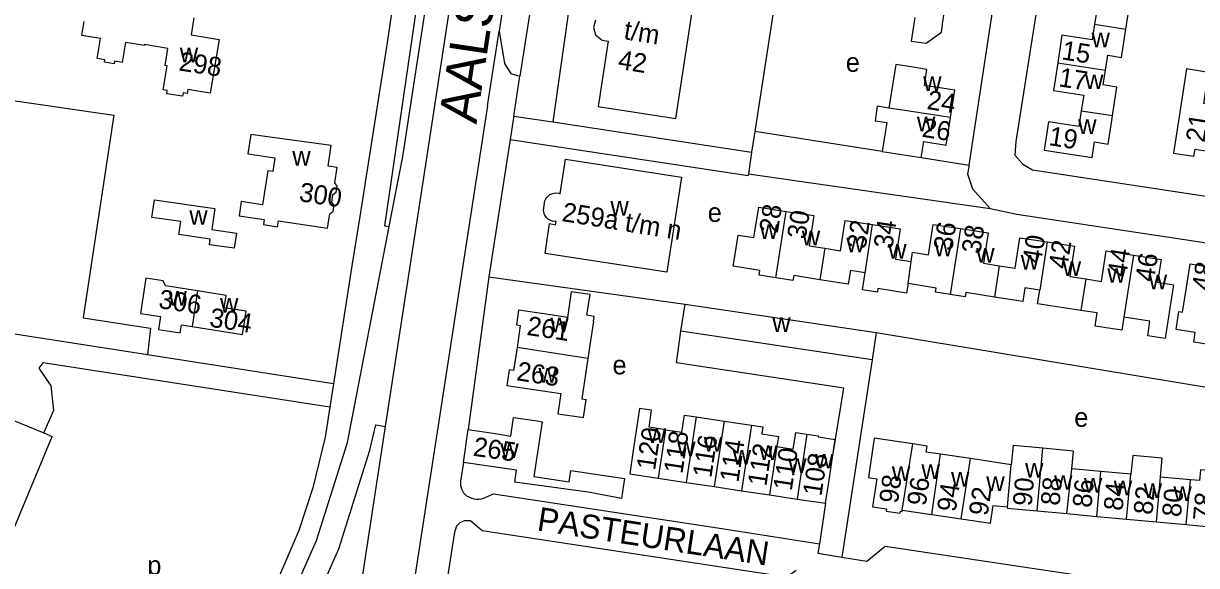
# Model space of a CAD drawing. Extents: x 161093 to 163177, y 379000 to 380904.
# Drawn here: x 161584.6 to 161831.1, y 380571.5 to 380685.4 of the extents above; entities that cross this region are included whole.
import ezdxf

# ---------------------------------------------------------------- set-up
doc = ezdxf.new("R2010")
doc.units = 0
for name, color, linetype in [('BLT_Basislijn', 7, 'Continuous'), ('BLT_Bebouwing', 7, 'Continuous'), ('BLT_Centroide', 7, 'Continuous'), ('BLT_Huisnummer', 7, 'Continuous'), ('BLT_Huisnummer_ tussenligend', 7, 'Continuous'), ('BLT_Huisnummer_reeks', 7, 'Continuous'), ('BLT_Onderverdeling_panden', 7, 'Continuous'), ('BLT_Straatnaam', 7, 'Continuous'), ('BLT_Straatnaam_hoofdweg', 7, 'Continuous'), ('BLT_Vlakafsluiter', 7, 'Continuous')]:
    doc.layers.add(name, color=color, linetype=linetype)

msp = doc.modelspace()

# ---------------------------------------------------------------- linework, layer by layer
at = {"layer": 'BLT_Basislijn'}
for p, q in [((161712.32, 380779.37), (161695.84, 380664.67)), ((161699.21, 380740.85), (161688.95, 380674.32)), ((161665.83, 380714.11), (161661.04, 380681.33)), ((161745.18, 380707.38), (161738.3, 380662.64)), ((161687.6, 380665.55), (161686.89, 380660.96)), ((161687.65, 380665.91), (161687.6, 380665.55)), ((161687.65, 380665.91), (161695.84, 380664.67)), ((161695.84, 380664.67), (161737.65, 380658.36)), ((161738.3, 380662.64), (161737.65, 380658.36)), ((161765.09, 380658.46), (161738.3, 380662.64)), ((161686.89, 380660.96), (161686.55, 380658.75)), ((161686.89, 380660.96), (161736.91, 380653.41)), ((161686.55, 380658.75), (161682.45, 380632.16)), ((161737.56, 380657.76), (161736.97, 380653.81)), ((161737.65, 380658.36), (161737.56, 380657.76)), ((161773.27, 380657.19), (161783.33, 380655.62)), ((161736.97, 380653.81), (161736.91, 380653.41)), ((161736.97, 380653.81), (161787.8, 380646.51)), ((161653.62, 380634.48), (161649.78, 380609.69)), ((161682.45, 380632.16), (161678.11, 380600.05)), ((161682.45, 380632.16), (161723.65, 380626.43)), ((161610.72, 380615.75), (161577.46, 380620.91)), ((161611.34, 380621.33), (161610.72, 380615.75)), ((161763.82, 380620.43), (161846.89, 380606.73)), ((161649.78, 380609.69), (161610.72, 380615.75)), ((161762.96, 380614.72), (161756.59, 380573.27)), ((161649.02, 380604.75), (161588.78, 380614.09)), ((161649.78, 380609.69), (161649.02, 380604.75)), ((161574.73, 380560.34), (161590.62, 380598.62)), ((161588.93, 380599.39), (161590.62, 380598.62)), ((161753.18, 380584.58), (161751.88, 380576.03)), ((161675.17, 380578.54), (161663.42, 380502.41)), ((161730.45, 380579.4), (161751.88, 380576.03)), ((161751.88, 380576.03), (161751.59, 380574.09)), ((161765.74, 380575.56), (161840.27, 380564.46)), ((161751.59, 380574.09), (161756.59, 380573.27))]:
    msp.add_line(p, q, dxfattribs=at)
for points in [[(161706.18, 380821.7), (161704.99, 380816.11), (161684.56, 380683.72)], [(161669.3, 380656.68), (161678.84, 380718.93), (161681.03, 380733.18), (161681.5, 380742.87), (161681.03, 380752.86), (161679.79, 380769.7), (161680.11, 380781.48), (161684.7, 380816.97)], [(161661.49, 380642.68), (161664.36, 380657.44), (161676.05, 380733.69), (161676.5, 380742.87), (161676.04, 380752.56), (161675.71, 380757.07)], [(161813.7, 380721.85), (161803.14, 380723.75), (161793.18, 380660.59), (161792.97, 380657.69), (161794.63, 380655.83), (161796.7, 380654.59), (161900, 380638.91), (161927.09, 380634.62), (161929.68, 380637), (161939.36, 380702.62), (161928.91, 380704.1)], [(161670.78, 380713.39), (161660.47, 380642.83), (161661.49, 380642.68)], [(161783.33, 380655.62), (161790.16, 380700.36), (161745.18, 380707.38)], [(161661.04, 380681.33), (161655.3, 380644.83), (161653.62, 380634.48)], [(161684.56, 380683.72), (161685.74, 380676.95), (161687.05, 380674.82), (161688.95, 380674.32)], [(161570.35, 380670.93), (161603.63, 380666.07), (161597.24, 380623.99)], [(161682.14, 380668.07), (161642.03, 380408.19)], [(161660.7, 380600.74), (161669.3, 380656.68)], [(161783.33, 380655.62), (161783.04, 380653.76), (161784.08, 380650.65), (161787.8, 380646.51)], [(161787.8, 380646.51), (161793.39, 380645.27), (161900, 380629.2), (161927.53, 380624.83)], [(161634.12, 380549.59), (161637.01, 380556.06), (161646.23, 380576.79), (161652.69, 380597.35), (161661.49, 380642.68)], [(161597.24, 380623.99), (161597.18, 380623.55), (161611.34, 380621.33)], [(161754.69, 380594.64), (161756.99, 380608.75), (161721.88, 380614.1), (161722.8, 380620.73)], [(161588.93, 380599.39), (161591, 380604.13), (161590.47, 380609.26), (161587.91, 380612.98), (161588.78, 380614.09)], [(161575.12, 380604.97), (161588.93, 380599.39)], [(161649.02, 380604.75), (161648.02, 380598.44), (161645.46, 380587.8), (161642.47, 380578.85), (161635.67, 380563.01), (161627, 380547.55), (161620.83, 380536.55), (161615.03, 380523.42)], [(161621.47, 380481.88), (161624.12, 380498.97), (161627.09, 380513.52), (161629.13, 380521.33), (161631.76, 380529.87), (161635.01, 380539.31), (161641.57, 380554.03), (161650.92, 380575.02), (161657.43, 380595.76), (161658.69, 380601.09), (161660.7, 380600.74)], [(161636.25, 380465.77), (161644.12, 380517.01), (161647.81, 380535.09), (161653.41, 380553.05), (161659.65, 380593.88), (161660.7, 380600.74)], [(161677.07, 380593.15), (161676.45, 380589.25), (161676.47, 380588.4), (161676.69, 380587.58), (161677.1, 380586.78), (161677.7, 380586.15), (161678.82, 380585.68), (161679.32, 380585.51), (161679.83, 380585.42), (161680.36, 380585.42), (161680.87, 380585.49), (161681.37, 380585.64), (161681.65, 380585.76)], [(161681.65, 380585.76), (161683.42, 380586.56), (161730.45, 380579.4)], [(161746.98, 380570.46), (161745.04, 380569.05), (161681.04, 380578.78), (161678.56, 380580.9), (161677.21, 380580.9), (161676.31, 380580.49), (161675.65, 380579.76), (161675.17, 380578.54)], [(161756.59, 380573.27), (161761.83, 380572.41), (161765.74, 380575.56)]]:
    msp.add_lwpolyline(points, dxfattribs=at)
at = {"layer": 'BLT_Bebouwing'}
for p, q in [((161698.55, 380656.88), (161722.93, 380653.09)), ((161765.09, 380658.46), (161773.27, 380657.19)), ((161722.8, 380620.73), (161723.65, 380626.43)), ((161723.65, 380626.43), (161763.82, 380620.43)), ((161704.39, 380622.8), (161703.22, 380614.96)), ((161762.96, 380614.72), (161722.8, 380620.73)), ((161763.82, 380620.43), (161762.96, 380614.72)), ((161725.98, 380602.73), (161731.84, 380601.84)), ((161677.07, 380593.15), (161678.11, 380600.05)), ((161731.84, 380601.84), (161737.61, 380600.98)), ((161811.04, 380591.26), (161804.93, 380591.82)), ((161817.31, 380590.68), (161811.04, 380591.26)), ((161829.85, 380589.53), (161823.58, 380590.1)), ((161718.02, 380589.84), (161723.92, 380588.96)), ((161723.92, 380588.96), (161729.75, 380588.08)), ((161729.75, 380588.08), (161735.55, 380587.22)), ((161735.55, 380587.22), (161741.4, 380586.34)), ((161741.4, 380586.34), (161747.24, 380585.47)), ((161747.24, 380585.47), (161753.18, 380584.58)), ((161769.29, 380583.15), (161775.48, 380582.22)), ((161797.63, 380582.98), (161803.9, 380582.4)), ((161775.48, 380582.22), (161781.67, 380581.3)), ((161803.9, 380582.4), (161810.17, 380581.82)), ((161810.17, 380581.82), (161816.44, 380581.24)), ((161816.44, 380581.24), (161822.71, 380580.67)), ((161822.71, 380580.67), (161828.98, 380580.09))]:
    msp.add_line(p, q, dxfattribs=at)
for points in [[(161704.8, 380686.03), (161704.38, 380684.51), (161704.86, 380682.96), (161706.25, 380681.83), (161707.47, 380681.61), (161705.38, 380667.94), (161721.71, 380665.43), (161736.53, 380762.16)], [(161771.92, 380686.59), (161771.19, 380681.67), (161774.3, 380681.19), (161777.52, 380683.54), (161777.85, 380685.68), (161778.28, 380688.52), (161784.82, 380687.51), (161785.92, 380694.44), (161782.64, 380694.96), (161783.14, 380698.11), (161777.21, 380699.03), (161776.24, 380692.65), (161772.92, 380693.15)], [(161804.76, 380695.28), (161803.87, 380689.49), (161810.24, 380688.51), (161809.73, 380685.21)], [(161816.27, 380684.19), (161817.67, 380693.29)], [(161620.45, 380686.54), (161619.86, 380682.96), (161625.72, 380681.99), (161623.88, 380670.74), (161619.15, 380671.51), (161619.01, 380670.63), (161618.15, 380670.77), (161618.04, 380670.08), (161614.73, 380670.6), (161614.84, 380671.29), (161613.99, 380671.43), (161614.81, 380676.48), (161614.38, 380676.56), (161614.96, 380680.11), (161610.06, 380680.91), (161610.03, 380680.72), (161606.04, 380681.36), (161605.38, 380677.15), (161603.75, 380677.41), (161603.67, 380676.91), (161601.67, 380677.23), (161601.75, 380677.74), (161600.13, 380678), (161600.8, 380682.23), (161596.89, 380682.85), (161597.35, 380685.79)], [(161809.73, 380685.21), (161809.22, 380681.9), (161802.85, 380682.88), (161801.96, 380677.09)], [(161812.02, 380675.54), (161812.5, 380678.67), (161815.36, 380678.23), (161816.27, 380684.19)], [(161779.45, 380665.58), (161780.33, 380671.36), (161773.99, 380672.34), (161774.48, 380675.72), (161771.17, 380676.23), (161767.94, 380676.73), (161766.51, 380667.58)], [(161801.96, 380677.09), (161801.06, 380671.31), (161807.43, 380670.32), (161806.92, 380667.02)], [(161813.47, 380666), (161814.4, 380672.01), (161811.54, 380672.45), (161812.02, 380675.54)], [(161836.89, 380667.91), (161832.67, 380668.56), (161833.67, 380675.08), (161829.03, 380675.8), (161827.07, 380663.06), (161826.3, 380658.11), (161830.6, 380657.46), (161830.82, 380658.94), (161835.41, 380658.23)], [(161766.51, 380667.58), (161764.05, 380667.96), (161763.58, 380664.93), (161766.05, 380664.54), (161765.09, 380658.46)], [(161806.92, 380667.02), (161806.41, 380663.71), (161800.04, 380664.7), (161799.12, 380658.77), (161809.21, 380657.21), (161809.71, 380660.48), (161812.56, 380660.04), (161813.32, 380664.99), (161813.47, 380666)], [(161773.27, 380657.19), (161773.8, 380660.55), (161778.56, 380659.8), (161779.45, 380665.58)], [(161635.97, 380654.41), (161634.87, 380647.27), (161630.39, 380647.96), (161629.93, 380644.97), (161635.21, 380644.16), (161635.05, 380643.14), (161638.02, 380642.67), (161638.22, 380643.93), (161648.52, 380642.34), (161648.99, 380645.4), (161649.71, 380645.93), (161649.9, 380647.15), (161649.42, 380647.82), (161649.67, 380649.44), (161650.35, 380649.94), (161650.55, 380651.19), (161650.04, 380651.88), (161650.53, 380655.08), (161648.65, 380655.37), (161649.32, 380659.72), (161637.45, 380661.34), (161632.38, 380662.03), (161631.76, 380658), (161637.45, 380657.12), (161637, 380654.25), (161635.97, 380654.41)], [(161722.93, 380653.09), (161719.83, 380633.13), (161694.27, 380637.05), (161695.18, 380643.33), (161696.41, 380643.09), (161696.54, 380643.77), (161696.31, 380643.76), (161695.83, 380643.8), (161695.35, 380643.98), (161694.96, 380644.21), (161694.63, 380644.52), (161694.36, 380644.85), (161694.12, 380645.26), (161693.97, 380645.71), (161693.89, 380646.17), (161694.21, 380648.09), (161694.4, 380648.5), (161694.62, 380648.8), (161694.91, 380649.12), (161695.27, 380649.42), (161695.66, 380649.59), (161696.17, 380649.72), (161696.64, 380649.76), (161697.1, 380649.7), (161697.39, 380649.6), (161698.55, 380656.88)], [(161734.79, 380640.92), (161738.14, 380640.4), (161739.13, 380646.77), (161744.92, 380645.89)], [(161744.92, 380645.89), (161750.71, 380645), (161749.73, 380638.65), (161753.03, 380638.14)], [(161753.03, 380638.14), (161756.33, 380637.63), (161757.31, 380643.98), (161763.07, 380643.1)], [(161763.07, 380643.1), (161768.88, 380642.21), (161767.89, 380635.84), (161771.17, 380635.33)], [(161771.17, 380635.33), (161771.47, 380637.29), (161774.81, 380636.77), (161775.8, 380643.16), (161781.57, 380642.26)], [(161781.57, 380642.26), (161787.34, 380641.37), (161786.36, 380634.98), (161789.68, 380634.47)], [(161742.74, 380631.92), (161739.24, 380632.46), (161739.4, 380633.49), (161733.77, 380634.36), (161734.02, 380635.98), (161734.79, 380640.92)], [(161789.68, 380634.47), (161793, 380633.96), (161793.98, 380640.35), (161799.74, 380639.47)], [(161799.74, 380639.47), (161805.51, 380638.58), (161804.54, 380632.2), (161807.85, 380631.69)], [(161807.85, 380631.69), (161811.17, 380631.19), (161812.14, 380637.57), (161817.91, 380636.68)], [(161817.91, 380636.68), (161823.68, 380635.78), (161822.95, 380630.99), (161826.33, 380630.48), (161825.56, 380625.54), (161824.57, 380619.2), (161820.88, 380619.77), (161821.36, 380622.85), (161815.88, 380623.7)], [(161837.97, 380625.17), (161836.78, 380617.45), (161830.56, 380618.41), (161830.88, 380620.44), (161826.85, 380621.06), (161827.44, 380624.87), (161828.21, 380624.75), (161829, 380629.9), (161829.77, 380634.84), (161835.7, 380633.93), (161835.18, 380630.68), (161838.73, 380630.11), (161837.97, 380625.17)], [(161752.01, 380631.54), (161746.48, 380632.4), (161746.32, 380631.36), (161742.74, 380631.92)], [(161761.51, 380632.99), (161758.4, 380633.48), (161757.96, 380630.62), (161752.01, 380631.54)], [(161770.52, 380630.71), (161770.21, 380628.73), (161764.18, 380629.66), (161764.07, 380628.94), (161760.94, 380629.44), (161761.51, 380632.99)], [(161621.19, 380629.18), (161614.44, 380630.22), (161613.98, 380631.33), (161610.34, 380631.89), (161609.19, 380624.47), (161613.45, 380623.81), (161613.03, 380621.06)], [(161779.4, 380628.42), (161776.3, 380628.9), (161776.43, 380629.79), (161770.52, 380630.71)], [(161798.19, 380629.35), (161795.05, 380629.84), (161794.61, 380626.98), (161788.67, 380627.9)], [(161620.04, 380621.7), (161630.67, 380620.06), (161631.42, 380624.92), (161626.8, 380625.64), (161627.2, 380628.25), (161621.19, 380629.18)], [(161704.39, 380622.8), (161704.54, 380623.83), (161703.04, 380624.06), (161703.69, 380628.4), (161699.72, 380628.99), (161698.95, 380623.58), (161694.5, 380624.28), (161688.67, 380625.15), (161688.2, 380622.03), (161689.02, 380621.91), (161688.34, 380617.31)], [(161788.67, 380627.9), (161782.66, 380628.83), (161782.52, 380627.94), (161779.4, 380628.42)], [(161806.85, 380625.09), (161797.72, 380626.5), (161798.19, 380629.35)], [(161815.88, 380623.7), (161815.45, 380620.92), (161809.84, 380621.79), (161810.27, 380624.56), (161806.85, 380625.09)], [(161613.03, 380621.06), (161617.55, 380620.37), (161617.81, 380622.04), (161620.04, 380621.7)], [(161688.34, 380617.31), (161687.61, 380612.48), (161686.66, 380612.62), (161686.17, 380609.31), (161697.57, 380607.61), (161696.94, 380603.38), (161701.89, 380602.64)], [(161703.22, 380614.96), (161701.95, 380606.52), (161702.85, 380606.36)], [(161701.89, 380602.64), (161702.28, 380602.58), (161702.85, 380606.36)], [(161687.05, 380598.71), (161687.63, 380602.61), (161692.58, 380601.87)], [(161719.54, 380600.03), (161716.08, 380600.54), (161716.62, 380604.12), (161714.08, 380604.5), (161712.76, 380595.68), (161712.02, 380590.74), (161718.02, 380589.84)], [(161719.54, 380600.03), (161723.01, 380599.51), (161723.55, 380603.1), (161725.98, 380602.73)], [(161678.11, 380600.05), (161683.77, 380599.21), (161687.05, 380598.71)], [(161692.58, 380601.87), (161693.6, 380601.72), (161691.87, 380590.21), (161699.27, 380589.1), (161699.62, 380591.47), (161710.95, 380589.77)], [(161737.61, 380600.98), (161740, 380600.62), (161739.78, 380599.16), (161743.27, 380598.63), (161742.92, 380596.48)], [(161742.92, 380596.48), (161746.38, 380595.96), (161746.91, 380599.48), (161749.28, 380599.12)], [(161749.28, 380599.12), (161751.65, 380598.77), (161751.62, 380598.53), (161755.19, 380597.98)], [(161753.18, 380584.58), (161753.84, 380589.01), (161755.19, 380597.98)], [(161771.49, 380597.05), (161763.43, 380598.25), (161762.2, 380589.97), (161763.95, 380589.71), (161763.07, 380583.82), (161766.02, 380583.38), (161765.95, 380582.94), (161768.87, 380582.51), (161768.93, 380582.89), (161769.25, 380582.84), (161769.29, 380583.15)], [(161777.35, 380594.9), (161774.32, 380595.35), (161774.53, 380596.59), (161771.49, 380597.05)], [(161798.85, 380596.15), (161792.58, 380596.73), (161792.21, 380592.68)], [(161804.93, 380591.82), (161805.27, 380595.56), (161798.85, 380596.15)], [(161688.23, 380591.57), (161677.07, 380593.15)], [(161783.63, 380593.96), (161777.35, 380594.9)], [(161792.21, 380592.68), (161783.63, 380593.96)], [(161823.58, 380590.1), (161823.95, 380594.03), (161817.76, 380594.6), (161817.31, 380590.68)], [(161687.85, 380589.04), (161688.23, 380591.57)], [(161828.98, 380580.09), (161835.25, 380579.51), (161835.43, 380581.49), (161839.87, 380581.08), (161840.72, 380590.85), (161831.99, 380591.62), (161831.77, 380589.35), (161829.85, 380589.53)], [(161710.32, 380585.61), (161703.31, 380586.94), (161687.85, 380589.04)], [(161710.95, 380589.77), (161710.32, 380585.61)], [(161781.67, 380581.3), (161787.85, 380580.37), (161788.41, 380584.1), (161791.39, 380583.82)], [(161791.39, 380583.82), (161791.36, 380583.55), (161797.63, 380582.98)]]:
    msp.add_lwpolyline(points, dxfattribs=at)
msp.add_lwpolyline([(161612.16, 380648.32), (161624.85, 380646.49), (161624.18, 380642.05), (161629.37, 380641.31), (161628.89, 380638.13), (161623.71, 380638.88), (161623.88, 380640.07), (161617.28, 380641.02), (161617.68, 380643.75), (161611.62, 380644.62)], close=True, dxfattribs=at)
at = {"layer": 'BLT_Onderverdeling_panden'}
for p, q in [((161809.73, 380685.21), (161816.27, 380684.19)), ((161801.96, 380677.09), (161812.02, 380675.54)), ((161806.92, 380667.02), (161813.47, 380666)), ((161742.74, 380631.92), (161744.92, 380645.89)), ((161761.51, 380632.99), (161763.07, 380643.1)), ((161781.57, 380642.26), (161779.4, 380628.42)), ((161799.74, 380639.47), (161798.19, 380629.35)), ((161753.03, 380638.14), (161752.01, 380631.54)), ((161770.52, 380630.71), (161771.17, 380635.33)), ((161789.68, 380634.47), (161788.67, 380627.9)), ((161817.91, 380636.68), (161815.88, 380623.7)), ((161807.85, 380631.69), (161806.85, 380625.09)), ((161621.19, 380629.18), (161620.04, 380621.7)), ((161703.22, 380614.96), (161688.34, 380617.31)), ((161725.98, 380602.73), (161723.92, 380588.96)), ((161719.54, 380600.03), (161718.02, 380589.84)), ((161731.84, 380601.84), (161729.75, 380588.08)), ((161737.61, 380600.98), (161735.55, 380587.22)), ((161749.28, 380599.12), (161747.24, 380585.47)), ((161742.92, 380596.48), (161741.4, 380586.34)), ((161769.29, 380583.15), (161771.49, 380597.05)), ((161797.63, 380582.98), (161798.85, 380596.15)), ((161775.48, 380582.22), (161777.35, 380594.9)), ((161781.67, 380581.3), (161783.63, 380593.96)), ((161791.39, 380583.82), (161792.21, 380592.68)), ((161803.9, 380582.4), (161804.93, 380591.82)), ((161810.17, 380581.82), (161811.04, 380591.26)), ((161816.44, 380581.24), (161817.31, 380590.68)), ((161822.71, 380580.67), (161823.58, 380590.1)), ((161828.98, 380580.09), (161829.85, 380589.53))]:
    msp.add_line(p, q, dxfattribs=at)
msp.add_lwpolyline([(161779.45, 380665.58), (161769.38, 380667.12), (161766.51, 380667.58)], dxfattribs=at)
at = {"layer": 'BLT_Vlakafsluiter'}
for p, q in [((161682.14, 380668.07), (161684.56, 380683.72)), ((161687.65, 380665.91), (161688.95, 380674.32))]:
    msp.add_line(p, q, dxfattribs=at)

# ---------------------------------------------------------------- texts
at = {"layer": 'BLT_Centroide'}
for s, p in [('w', (161809.08, 380680.38)), ('w', (161617.47, 380677.2)), ('e', (161757.43, 380675.21)), ('w', (161773.69, 380671.16)), ('w', (161807.71, 380671.56)), ('w', (161772.38, 380662.69)), ('w', (161806.26, 380662.12)), ('w', (161641.11, 380655.51)), ('w', (161707.97, 380645)), ('e', (161728.42, 380643.68)), ('w', (161619.47, 380643.07)), ('w', (161739.34, 380640.12)), ('w', (161748.19, 380638.75)), ('w', (161757.55, 380637.31)), ('w', (161776.05, 380636.48)), ('w', (161766.34, 380635.95)), ('w', (161784.84, 380635.12)), ('w', (161794.2, 380633.67)), ('w', (161803.02, 380632.33)), ('w', (161812.38, 380630.89)), ('w', (161821.11, 380629.53)), ('w', (161615.09, 380626.12)), ('w', (161625.93, 380624.62)), ('w', (161695.33, 380620.5)), ('w', (161741.98, 380620.56)), ('e', (161708.41, 380611.65)), ('w', (161692.85, 380609.94)), ('e', (161805.44, 380600.64)), ('w', (161715.78, 380597.22)), ('w', (161722, 380594.45)), ('w', (161727.59, 380595.45)), ('w', (161684.84, 380594.12)), ('w', (161733.67, 380592.7)), ('w', (161739.23, 380593.7)), ('w', (161745.34, 380590.94)), ('w', (161750.97, 380591.89)), ('w', (161773.33, 380589.66)), ('w', (161795.11, 380589.98)), ('w', (161767.12, 380589.25)), ('w', (161779.55, 380588.09)), ('w', (161786.95, 380587.14)), ('w', (161801.2, 380587.41)), ('w', (161807.47, 380586.83)), ('w', (161813.75, 380586.25)), ('w', (161820.02, 380585.67)), ('w', (161826.28, 380585.09)), ('p', (161610.64, 380569.55))]:
    msp.add_text(s, height=4, dxfattribs=at).set_placement(p)
at = {"layer": 'BLT_Huisnummer'}
for s, rotation, p in [('15', 351.2055, (161802.65, 380677.84)), ('298', 351.244, (161617.12, 380675.52)), ('24', 351.2859, (161774.32, 380667.41)), ('26', 351.0867, (161773.29, 380661.59)), ('21', 81.2699, (161832.79, 380660.22)), ('19', 351.2244, (161799.93, 380659.82)), ('300', 351.2413, (161642.38, 380648.07)), ('28', 81.1296, (161743.13, 380641.18)), ('34', 81.1443, (161767.18, 380637.88)), ('38', 81.266, (161785.68, 380636.85)), ('42', 81.3415, (161803.96, 380633.65)), ('46', 81.3868, (161822.18, 380630.95)), ('48', 80.8753, (161834.05, 380629.06)), ('306', 351.2428, (161612.86, 380625.6)), ('304', 351.2434, (161623.54, 380621.7)), ('261', 351.5072, (161690.24, 380619.96)), ('263', 351.4926, (161688.09, 380610.44)), ('120', 81.5025, (161717.34, 380591.38)), ('265', 351.9473, (161678.96, 380594.58)), ('116', 81.4956, (161729.17, 380589.8)), ('112', 81.4969, (161740.73, 380588.02)), ('108', 81.4926, (161752.31, 380585.96)), ('98', 82.0744, (161768.36, 380584.42)), ('92', 81.4956, (161787.21, 380581.8)), ('90', 84.7377, (161796.48, 380583.88)), ('86', 84.7437, (161809.04, 380583.55)), ('82', 84.7371, (161821.87, 380582.07)), ('78', 84.7429, (161834.34, 380580.76))]:
    msp.add_text(s, height=4, rotation=rotation, dxfattribs=at).set_placement(p)
at = {"layer": 'BLT_Huisnummer_ tussenligend'}
for s, rotation, p in [('17', 351.2055, (161802.01, 380672.18)), ('30', 81.1296, (161748.99, 380639.91)), ('32', 81.1296, (161761.57, 380637.83)), ('36', 81.1443, (161779.76, 380637.46)), ('40', 81.266, (161798.46, 380634.74)), ('44', 81.3415, (161816.33, 380631.95)), ('118', 81.4956, (161723.09, 380590.65)), ('114', 81.4969, (161734.86, 380588.85)), ('110', 81.4926, (161746.07, 380587.08)), ('96', 81.4956, (161774.22, 380583.88)), ('94', 81.4956, (161780.51, 380582.62)), ('88', 84.7437, (161802.34, 380583.98)), ('84', 84.7371, (161815.59, 380582.89)), ('80', 84.7429, (161827.84, 380581.59))]:
    msp.add_text(s, height=4, rotation=rotation, dxfattribs=at).set_placement(p)
at = {"layer": 'BLT_Huisnummer_reeks'}
for s, rotation, p in [('t/m', 350.8518, (161710.63, 380682.1)), ('42', 350.8521, (161709.4, 380675.87)), ('259a t/m n', 350.8518, (161697.61, 380643.88))]:
    msp.add_text(s, height=4, rotation=rotation, dxfattribs=at).set_placement(p)
at = {"layer": 'BLT_Straatnaam'}
msp.add_text('PASTEURLAAN', height=5, rotation=351.3008, dxfattribs=at).set_placement((161692.38, 380578.89))
at = {"layer": 'BLT_Straatnaam_hoofdweg'}
msp.add_text('AALSTERWEG', height=8, rotation=81.4709, dxfattribs=at).set_placement((161679.81, 380664.08))

doc.saveas('drawing.dxf')
